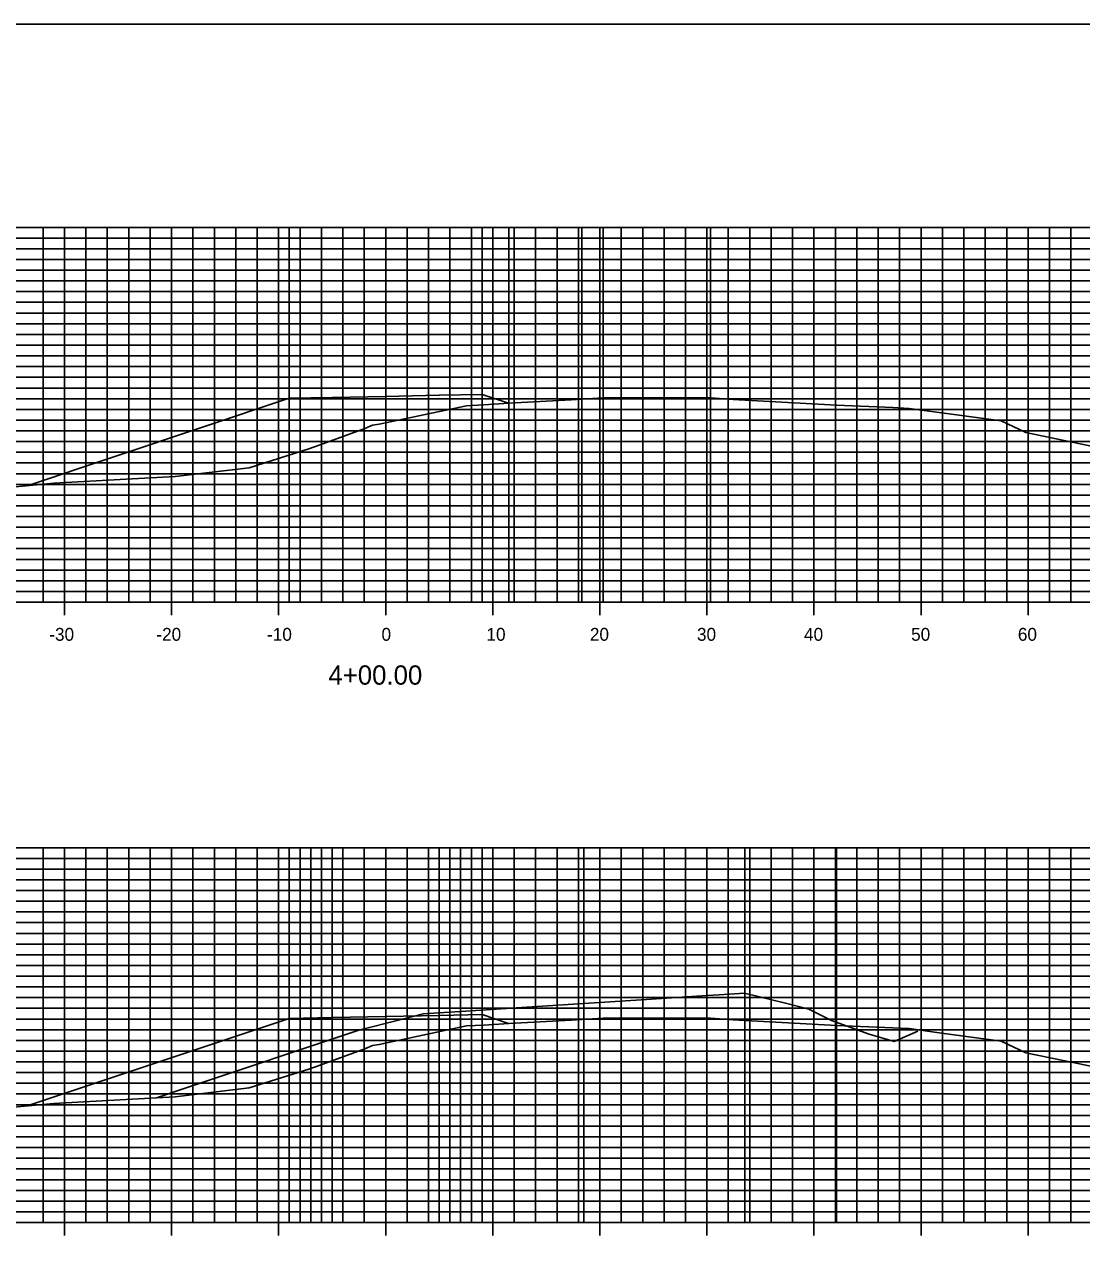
# Model space of a CAD drawing. Extents: x 1405440 to 1409538, y 1842123 to 1843178.
# Drawn here: x 1408848.9 to 1408947.6, y 1842829.8 to 1842943.5 of the extents above; entities that cross this region are included whole.
import ezdxf

# ---------------------------------------------------------------- set-up
doc = ezdxf.new("R2010")
doc.units = 0
for name, color, linetype in [('R_Axis Annot', 7, 'Continuous'), ('R_Exist Surface', 7, 'Continuous'), ('R_Grid_Minor', 7, 'Continuous'), ('R_Grid_Sta', 7, 'Continuous'), ('R_Grid_Tick', 7, 'Continuous'), ('R_Prop Surface', 7, 'Continuous'), ('S_DITCHLINE', 7, 'Continuous'), ('Stage 1_Construction', 7, 'Continuous'), ('Stage 1_Lane', 7, 'Continuous'), ('Stage 1_Removal', 7, 'Continuous'), ('Stage 1_Stripe_4IN_White', 7, 'Continuous'), ('Stage 2_Barrier', 7, 'Continuous'), ('Stage 2_Construction', 7, 'Continuous'), ('Stage 2_Stripe_4IN_White', 7, 'Continuous')]:
    doc.layers.add(name, color=color, linetype=linetype)

msp = doc.modelspace()

# ---------------------------------------------------------------- linework, layer by layer
for p, q in [((1408732.62, 1842924.51), (1409032.62, 1842924.51)), ((1408852.62, 1842889.51), (1408852.62, 1842924.51)), ((1408862.62, 1842889.51), (1408862.62, 1842924.51)), ((1408872.62, 1842889.51), (1408872.62, 1842924.51)), ((1408882.62, 1842889.51), (1408882.62, 1842924.51)), ((1408892.62, 1842889.51), (1408892.62, 1842924.51)), ((1408902.62, 1842889.51), (1408902.62, 1842924.51)), ((1408912.62, 1842889.51), (1408912.62, 1842924.51)), ((1408922.62, 1842889.51), (1408922.62, 1842924.51)), ((1408932.62, 1842889.51), (1408932.62, 1842924.51)), ((1408942.62, 1842889.51), (1408942.62, 1842924.51)), ((1408732.62, 1842919.51), (1409032.62, 1842919.51)), ((1408732.62, 1842914.51), (1409032.62, 1842914.51)), ((1408732.62, 1842909.51), (1409032.62, 1842909.51)), ((1408732.62, 1842904.51), (1409032.62, 1842904.51)), ((1408732.62, 1842899.51), (1409032.62, 1842899.51)), ((1408732.62, 1842894.51), (1409032.62, 1842894.51)), ((1408732.62, 1842889.51), (1409032.62, 1842889.51)), ((1408732.62, 1842889.51), (1409032.62, 1842889.51)), ((1408732.62, 1842866.59), (1409032.62, 1842866.59)), ((1408852.62, 1842831.59), (1408852.62, 1842866.59)), ((1408862.62, 1842831.59), (1408862.62, 1842866.59)), ((1408872.62, 1842831.59), (1408872.62, 1842866.59)), ((1408882.62, 1842831.59), (1408882.62, 1842866.59)), ((1408892.62, 1842831.59), (1408892.62, 1842866.59)), ((1408902.62, 1842831.59), (1408902.62, 1842866.59)), ((1408912.62, 1842831.59), (1408912.62, 1842866.59)), ((1408922.62, 1842831.59), (1408922.62, 1842866.59)), ((1408932.62, 1842831.59), (1408932.62, 1842866.59)), ((1408942.62, 1842831.59), (1408942.62, 1842866.59)), ((1408732.62, 1842861.59), (1409032.62, 1842861.59)), ((1408732.62, 1842856.59), (1409032.62, 1842856.59)), ((1408732.62, 1842851.59), (1409032.62, 1842851.59)), ((1408732.62, 1842846.59), (1409032.62, 1842846.59)), ((1408732.62, 1842841.59), (1409032.62, 1842841.59)), ((1408732.62, 1842836.59), (1409032.62, 1842836.59)), ((1408732.62, 1842831.59), (1409032.62, 1842831.59)), ((1408732.62, 1842831.59), (1409032.62, 1842831.59))]:
    msp.add_line(p, q)
msp.add_lwpolyline([(1408707.62, 1842723.47), (1409047.62, 1842723.47), (1409047.62, 1842943.47), (1408707.62, 1842943.47)], close=True)
at = {"layer": 'R_Exist Surface'}
for points in [[(1408845.09, 1842900.01), (1408851.63, 1842900.62), (1408858.38, 1842901), (1408858.39, 1842901), (1408862.96, 1842901.25), (1408869.87, 1842902.07), (1408875.44, 1842903.83), (1408876.4, 1842904.16), (1408880.67, 1842905.72), (1408881.4, 1842906.03), (1408882, 1842906.14), (1408890.18, 1842907.86), (1408891.78, 1842907.94), (1408894.12, 1842908.09), (1408899.94, 1842908.4), (1408902.94, 1842908.59), (1408908.78, 1842908.6), (1408912.97, 1842908.58), (1408915.06, 1842908.44), (1408924.71, 1842907.9), (1408929.98, 1842907.68), (1408931.51, 1842907.61), (1408934.3, 1842907.22), (1408940.11, 1842906.44), (1408942.42, 1842905.36), (1408951.8, 1842903.41)], [(1408845.09, 1842842.1), (1408851.63, 1842842.71), (1408858.38, 1842843.09), (1408858.39, 1842843.09), (1408862.96, 1842843.33), (1408869.87, 1842844.15), (1408875.44, 1842845.91), (1408876.4, 1842846.24), (1408880.67, 1842847.8), (1408881.4, 1842848.11), (1408882, 1842848.22), (1408890.18, 1842849.94), (1408891.78, 1842850.02), (1408894.12, 1842850.18), (1408899.94, 1842850.48), (1408902.94, 1842850.68), (1408908.78, 1842850.68), (1408912.97, 1842850.66), (1408915.06, 1842850.52), (1408924.71, 1842849.99), (1408929.98, 1842849.76), (1408931.51, 1842849.69), (1408934.3, 1842849.3), (1408940.11, 1842848.53), (1408942.42, 1842847.44), (1408951.8, 1842845.5)]]:
    msp.add_lwpolyline(points, dxfattribs=at)
at = {"layer": 'R_Grid_Minor'}
for p, q in [((1408850.62, 1842889.51), (1408850.62, 1842924.51)), ((1408854.62, 1842889.51), (1408854.62, 1842924.51)), ((1408856.62, 1842889.51), (1408856.62, 1842924.51)), ((1408858.62, 1842889.51), (1408858.62, 1842924.51)), ((1408860.62, 1842889.51), (1408860.62, 1842924.51)), ((1408864.62, 1842889.51), (1408864.62, 1842924.51)), ((1408866.62, 1842889.51), (1408866.62, 1842924.51)), ((1408868.62, 1842889.51), (1408868.62, 1842924.51)), ((1408870.62, 1842889.51), (1408870.62, 1842924.51)), ((1408874.62, 1842889.51), (1408874.62, 1842924.51)), ((1408876.62, 1842889.51), (1408876.62, 1842924.51)), ((1408878.62, 1842889.51), (1408878.62, 1842924.51)), ((1408880.62, 1842889.51), (1408880.62, 1842924.51)), ((1408884.62, 1842889.51), (1408884.62, 1842924.51)), ((1408886.62, 1842889.51), (1408886.62, 1842924.51)), ((1408888.62, 1842889.51), (1408888.62, 1842924.51)), ((1408890.62, 1842889.51), (1408890.62, 1842924.51)), ((1408894.62, 1842889.51), (1408894.62, 1842924.51)), ((1408896.62, 1842889.51), (1408896.62, 1842924.51)), ((1408898.62, 1842889.51), (1408898.62, 1842924.51)), ((1408900.62, 1842889.51), (1408900.62, 1842924.51)), ((1408904.62, 1842889.51), (1408904.62, 1842924.51)), ((1408906.62, 1842889.51), (1408906.62, 1842924.51)), ((1408908.62, 1842889.51), (1408908.62, 1842924.51)), ((1408910.62, 1842889.51), (1408910.62, 1842924.51)), ((1408914.62, 1842889.51), (1408914.62, 1842924.51)), ((1408916.62, 1842889.51), (1408916.62, 1842924.51)), ((1408918.62, 1842889.51), (1408918.62, 1842924.51)), ((1408920.62, 1842889.51), (1408920.62, 1842924.51)), ((1408924.62, 1842889.51), (1408924.62, 1842924.51)), ((1408926.62, 1842889.51), (1408926.62, 1842924.51)), ((1408928.62, 1842889.51), (1408928.62, 1842924.51)), ((1408930.62, 1842889.51), (1408930.62, 1842924.51)), ((1408934.62, 1842889.51), (1408934.62, 1842924.51)), ((1408936.62, 1842889.51), (1408936.62, 1842924.51)), ((1408938.62, 1842889.51), (1408938.62, 1842924.51)), ((1408940.62, 1842889.51), (1408940.62, 1842924.51)), ((1408944.62, 1842889.51), (1408944.62, 1842924.51)), ((1408946.62, 1842889.51), (1408946.62, 1842924.51)), ((1408732.62, 1842923.51), (1409032.62, 1842923.51)), ((1408732.62, 1842922.51), (1409032.62, 1842922.51)), ((1408732.62, 1842921.51), (1409032.62, 1842921.51)), ((1408732.62, 1842920.51), (1409032.62, 1842920.51)), ((1408732.62, 1842918.51), (1409032.62, 1842918.51)), ((1408732.62, 1842917.51), (1409032.62, 1842917.51)), ((1408732.62, 1842916.51), (1409032.62, 1842916.51)), ((1408732.62, 1842915.51), (1409032.62, 1842915.51)), ((1408732.62, 1842913.51), (1409032.62, 1842913.51)), ((1408732.62, 1842912.51), (1409032.62, 1842912.51)), ((1408732.62, 1842911.51), (1409032.62, 1842911.51)), ((1408732.62, 1842910.51), (1409032.62, 1842910.51)), ((1408732.62, 1842908.51), (1409032.62, 1842908.51)), ((1408732.62, 1842907.51), (1409032.62, 1842907.51)), ((1408732.62, 1842906.51), (1409032.62, 1842906.51)), ((1408732.62, 1842905.51), (1409032.62, 1842905.51)), ((1408732.62, 1842903.51), (1409032.62, 1842903.51)), ((1408732.62, 1842902.51), (1409032.62, 1842902.51)), ((1408732.62, 1842901.51), (1409032.62, 1842901.51)), ((1408732.62, 1842900.51), (1409032.62, 1842900.51)), ((1408732.62, 1842898.51), (1409032.62, 1842898.51)), ((1408732.62, 1842897.51), (1409032.62, 1842897.51)), ((1408732.62, 1842896.51), (1409032.62, 1842896.51)), ((1408732.62, 1842895.51), (1409032.62, 1842895.51)), ((1408732.62, 1842893.51), (1409032.62, 1842893.51)), ((1408732.62, 1842892.51), (1409032.62, 1842892.51)), ((1408732.62, 1842891.51), (1409032.62, 1842891.51)), ((1408732.62, 1842890.51), (1409032.62, 1842890.51)), ((1408850.62, 1842831.59), (1408850.62, 1842866.59)), ((1408854.62, 1842831.59), (1408854.62, 1842866.59)), ((1408856.62, 1842831.59), (1408856.62, 1842866.59)), ((1408858.62, 1842831.59), (1408858.62, 1842866.59)), ((1408860.62, 1842831.59), (1408860.62, 1842866.59)), ((1408864.62, 1842831.59), (1408864.62, 1842866.59)), ((1408866.62, 1842831.59), (1408866.62, 1842866.59)), ((1408868.62, 1842831.59), (1408868.62, 1842866.59)), ((1408870.62, 1842831.59), (1408870.62, 1842866.59)), ((1408874.62, 1842831.59), (1408874.62, 1842866.59)), ((1408876.62, 1842831.59), (1408876.62, 1842866.59)), ((1408878.62, 1842831.59), (1408878.62, 1842866.59)), ((1408880.62, 1842831.59), (1408880.62, 1842866.59)), ((1408884.62, 1842831.59), (1408884.62, 1842866.59)), ((1408886.62, 1842831.59), (1408886.62, 1842866.59)), ((1408888.62, 1842831.59), (1408888.62, 1842866.59)), ((1408890.62, 1842831.59), (1408890.62, 1842866.59)), ((1408894.62, 1842831.59), (1408894.62, 1842866.59)), ((1408896.62, 1842831.59), (1408896.62, 1842866.59)), ((1408898.62, 1842831.59), (1408898.62, 1842866.59)), ((1408900.62, 1842831.59), (1408900.62, 1842866.59)), ((1408904.62, 1842831.59), (1408904.62, 1842866.59)), ((1408906.62, 1842831.59), (1408906.62, 1842866.59)), ((1408908.62, 1842831.59), (1408908.62, 1842866.59)), ((1408910.62, 1842831.59), (1408910.62, 1842866.59)), ((1408914.62, 1842831.59), (1408914.62, 1842866.59)), ((1408916.62, 1842831.59), (1408916.62, 1842866.59)), ((1408918.62, 1842831.59), (1408918.62, 1842866.59)), ((1408920.62, 1842831.59), (1408920.62, 1842866.59)), ((1408924.62, 1842831.59), (1408924.62, 1842866.59)), ((1408926.62, 1842831.59), (1408926.62, 1842866.59)), ((1408928.62, 1842831.59), (1408928.62, 1842866.59)), ((1408930.62, 1842831.59), (1408930.62, 1842866.59)), ((1408934.62, 1842831.59), (1408934.62, 1842866.59)), ((1408936.62, 1842831.59), (1408936.62, 1842866.59)), ((1408938.62, 1842831.59), (1408938.62, 1842866.59)), ((1408940.62, 1842831.59), (1408940.62, 1842866.59)), ((1408944.62, 1842831.59), (1408944.62, 1842866.59)), ((1408946.62, 1842831.59), (1408946.62, 1842866.59)), ((1408732.62, 1842865.59), (1409032.62, 1842865.59)), ((1408732.62, 1842864.59), (1409032.62, 1842864.59)), ((1408732.62, 1842863.59), (1409032.62, 1842863.59)), ((1408732.62, 1842862.59), (1409032.62, 1842862.59)), ((1408732.62, 1842860.59), (1409032.62, 1842860.59)), ((1408732.62, 1842859.59), (1409032.62, 1842859.59)), ((1408732.62, 1842858.59), (1409032.62, 1842858.59)), ((1408732.62, 1842857.59), (1409032.62, 1842857.59)), ((1408732.62, 1842855.59), (1409032.62, 1842855.59)), ((1408732.62, 1842854.59), (1409032.62, 1842854.59)), ((1408732.62, 1842853.59), (1409032.62, 1842853.59)), ((1408732.62, 1842852.59), (1409032.62, 1842852.59)), ((1408732.62, 1842850.59), (1409032.62, 1842850.59)), ((1408732.62, 1842849.59), (1409032.62, 1842849.59)), ((1408732.62, 1842848.59), (1409032.62, 1842848.59)), ((1408732.62, 1842847.59), (1409032.62, 1842847.59)), ((1408732.62, 1842845.59), (1409032.62, 1842845.59)), ((1408732.62, 1842844.59), (1409032.62, 1842844.59)), ((1408732.62, 1842843.59), (1409032.62, 1842843.59)), ((1408732.62, 1842842.59), (1409032.62, 1842842.59)), ((1408732.62, 1842840.59), (1409032.62, 1842840.59)), ((1408732.62, 1842839.59), (1409032.62, 1842839.59)), ((1408732.62, 1842838.59), (1409032.62, 1842838.59)), ((1408732.62, 1842837.59), (1409032.62, 1842837.59)), ((1408732.62, 1842835.59), (1409032.62, 1842835.59)), ((1408732.62, 1842834.59), (1409032.62, 1842834.59)), ((1408732.62, 1842833.59), (1409032.62, 1842833.59)), ((1408732.62, 1842832.59), (1409032.62, 1842832.59))]:
    msp.add_line(p, q, dxfattribs=at)
at = {"layer": 'R_Grid_Tick'}
for p, q in [((1408850.62, 1842889.51), (1408850.62, 1842890.11)), ((1408852.62, 1842888.31), (1408852.62, 1842890.71)), ((1408854.62, 1842889.51), (1408854.62, 1842890.11)), ((1408856.62, 1842889.51), (1408856.62, 1842890.11)), ((1408858.62, 1842889.51), (1408858.62, 1842890.11)), ((1408860.62, 1842889.51), (1408860.62, 1842890.11)), ((1408862.62, 1842888.31), (1408862.62, 1842890.71)), ((1408864.62, 1842889.51), (1408864.62, 1842890.11)), ((1408866.62, 1842889.51), (1408866.62, 1842890.11)), ((1408868.62, 1842889.51), (1408868.62, 1842890.11)), ((1408870.62, 1842889.51), (1408870.62, 1842890.11)), ((1408872.62, 1842888.31), (1408872.62, 1842890.71)), ((1408874.62, 1842889.51), (1408874.62, 1842890.11)), ((1408876.62, 1842889.51), (1408876.62, 1842890.11)), ((1408878.62, 1842889.51), (1408878.62, 1842890.11)), ((1408880.62, 1842889.51), (1408880.62, 1842890.11)), ((1408882.62, 1842888.31), (1408882.62, 1842890.71)), ((1408884.62, 1842889.51), (1408884.62, 1842890.11)), ((1408886.62, 1842889.51), (1408886.62, 1842890.11)), ((1408888.62, 1842889.51), (1408888.62, 1842890.11)), ((1408890.62, 1842889.51), (1408890.62, 1842890.11)), ((1408892.62, 1842888.31), (1408892.62, 1842890.71)), ((1408894.62, 1842889.51), (1408894.62, 1842890.11)), ((1408896.62, 1842889.51), (1408896.62, 1842890.11)), ((1408898.62, 1842889.51), (1408898.62, 1842890.11)), ((1408900.62, 1842889.51), (1408900.62, 1842890.11)), ((1408902.62, 1842888.31), (1408902.62, 1842890.71)), ((1408904.62, 1842889.51), (1408904.62, 1842890.11)), ((1408906.62, 1842889.51), (1408906.62, 1842890.11)), ((1408908.62, 1842889.51), (1408908.62, 1842890.11)), ((1408910.62, 1842889.51), (1408910.62, 1842890.11)), ((1408912.62, 1842888.31), (1408912.62, 1842890.71)), ((1408914.62, 1842889.51), (1408914.62, 1842890.11)), ((1408916.62, 1842889.51), (1408916.62, 1842890.11)), ((1408918.62, 1842889.51), (1408918.62, 1842890.11)), ((1408920.62, 1842889.51), (1408920.62, 1842890.11)), ((1408922.62, 1842888.31), (1408922.62, 1842890.71)), ((1408924.62, 1842889.51), (1408924.62, 1842890.11)), ((1408926.62, 1842889.51), (1408926.62, 1842890.11)), ((1408928.62, 1842889.51), (1408928.62, 1842890.11)), ((1408930.62, 1842889.51), (1408930.62, 1842890.11)), ((1408932.62, 1842888.31), (1408932.62, 1842890.71)), ((1408934.62, 1842889.51), (1408934.62, 1842890.11)), ((1408936.62, 1842889.51), (1408936.62, 1842890.11)), ((1408938.62, 1842889.51), (1408938.62, 1842890.11)), ((1408940.62, 1842889.51), (1408940.62, 1842890.11)), ((1408942.62, 1842888.31), (1408942.62, 1842890.71)), ((1408944.62, 1842889.51), (1408944.62, 1842890.11)), ((1408946.62, 1842889.51), (1408946.62, 1842890.11)), ((1408850.62, 1842831.59), (1408850.62, 1842832.19)), ((1408852.62, 1842830.39), (1408852.62, 1842832.79)), ((1408854.62, 1842831.59), (1408854.62, 1842832.19)), ((1408856.62, 1842831.59), (1408856.62, 1842832.19)), ((1408858.62, 1842831.59), (1408858.62, 1842832.19)), ((1408860.62, 1842831.59), (1408860.62, 1842832.19)), ((1408862.62, 1842830.39), (1408862.62, 1842832.79)), ((1408864.62, 1842831.59), (1408864.62, 1842832.19)), ((1408866.62, 1842831.59), (1408866.62, 1842832.19)), ((1408868.62, 1842831.59), (1408868.62, 1842832.19)), ((1408870.62, 1842831.59), (1408870.62, 1842832.19)), ((1408872.62, 1842830.39), (1408872.62, 1842832.79)), ((1408874.62, 1842831.59), (1408874.62, 1842832.19)), ((1408876.62, 1842831.59), (1408876.62, 1842832.19)), ((1408878.62, 1842831.59), (1408878.62, 1842832.19)), ((1408880.62, 1842831.59), (1408880.62, 1842832.19)), ((1408882.62, 1842830.39), (1408882.62, 1842832.79)), ((1408884.62, 1842831.59), (1408884.62, 1842832.19)), ((1408886.62, 1842831.59), (1408886.62, 1842832.19)), ((1408888.62, 1842831.59), (1408888.62, 1842832.19)), ((1408890.62, 1842831.59), (1408890.62, 1842832.19)), ((1408892.62, 1842830.39), (1408892.62, 1842832.79)), ((1408894.62, 1842831.59), (1408894.62, 1842832.19)), ((1408896.62, 1842831.59), (1408896.62, 1842832.19)), ((1408898.62, 1842831.59), (1408898.62, 1842832.19)), ((1408900.62, 1842831.59), (1408900.62, 1842832.19)), ((1408902.62, 1842830.39), (1408902.62, 1842832.79)), ((1408904.62, 1842831.59), (1408904.62, 1842832.19)), ((1408906.62, 1842831.59), (1408906.62, 1842832.19)), ((1408908.62, 1842831.59), (1408908.62, 1842832.19)), ((1408910.62, 1842831.59), (1408910.62, 1842832.19)), ((1408912.62, 1842830.39), (1408912.62, 1842832.79)), ((1408914.62, 1842831.59), (1408914.62, 1842832.19)), ((1408916.62, 1842831.59), (1408916.62, 1842832.19)), ((1408918.62, 1842831.59), (1408918.62, 1842832.19)), ((1408920.62, 1842831.59), (1408920.62, 1842832.19)), ((1408922.62, 1842830.39), (1408922.62, 1842832.79)), ((1408924.62, 1842831.59), (1408924.62, 1842832.19)), ((1408926.62, 1842831.59), (1408926.62, 1842832.19)), ((1408928.62, 1842831.59), (1408928.62, 1842832.19)), ((1408930.62, 1842831.59), (1408930.62, 1842832.19)), ((1408932.62, 1842830.39), (1408932.62, 1842832.79)), ((1408934.62, 1842831.59), (1408934.62, 1842832.19)), ((1408936.62, 1842831.59), (1408936.62, 1842832.19)), ((1408938.62, 1842831.59), (1408938.62, 1842832.19)), ((1408940.62, 1842831.59), (1408940.62, 1842832.19)), ((1408942.62, 1842830.39), (1408942.62, 1842832.79)), ((1408944.62, 1842831.59), (1408944.62, 1842832.19)), ((1408946.62, 1842831.59), (1408946.62, 1842832.19))]:
    msp.add_line(p, q, dxfattribs=at)
at = {"layer": 'R_Prop Surface'}
for points in [[(1408849.13, 1842900.39), (1408873.62, 1842908.55), (1408877.62, 1842908.63), (1408882.62, 1842908.73), (1408887.62, 1842908.83), (1408891.62, 1842908.91), (1408894.09, 1842908.09)], [(1408861.2, 1842843.24), (1408863.72, 1842844.08), (1408880.11, 1842849.55), (1408884.06, 1842850.54), (1408886.12, 1842851.06), (1408888.58, 1842851.22), (1408890.12, 1842851.32), (1408894.83, 1842851.62), (1408901.13, 1842852.04), (1408906.97, 1842852.41), (1408912.14, 1842852.75), (1408913.76, 1842852.86), (1408916.14, 1842853.01), (1408919.96, 1842852.06), (1408922.15, 1842851.51), (1408924.25, 1842850.46), (1408927.77, 1842849.19), (1408930.11, 1842848.48), (1408932.33, 1842849.45)], [(1408849.13, 1842842.47), (1408873.62, 1842850.64), (1408877.62, 1842850.72), (1408882.62, 1842850.82), (1408887.62, 1842850.92), (1408891.62, 1842851), (1408894.09, 1842850.17)]]:
    msp.add_lwpolyline(points, dxfattribs=at)
at = {"layer": 'S_DITCHLINE'}
msp.add_line((1408924.71, 1842831.59), (1408924.71, 1842866.59), dxfattribs=at)
at = {"layer": 'Stage 1_Construction'}
for p, q in [((1408873.62, 1842889.51), (1408873.62, 1842924.51)), ((1408891.62, 1842889.51), (1408891.62, 1842924.51))]:
    msp.add_line(p, q, dxfattribs=at)
at = {"layer": 'Stage 1_Lane'}
msp.add_line((1408912.97, 1842889.51), (1408912.97, 1842924.51), dxfattribs=at)
at = {"layer": 'Stage 1_Removal'}
for p, q in [((1408894.12, 1842889.51), (1408894.12, 1842924.51)), ((1408900.94, 1842889.51), (1408900.94, 1842924.51))]:
    msp.add_line(p, q, dxfattribs=at)
at = {"layer": 'Stage 1_Stripe_4IN_White'}
msp.add_line((1408902.94, 1842889.51), (1408902.94, 1842924.51), dxfattribs=at)
at = {"layer": 'Stage 2_Barrier'}
for p, q in [((1408873.62, 1842831.59), (1408873.62, 1842866.59)), ((1408875.62, 1842831.59), (1408875.62, 1842866.59)), ((1408889.62, 1842831.59), (1408889.62, 1842866.59)), ((1408891.62, 1842831.59), (1408891.62, 1842866.59))]:
    msp.add_line(p, q, dxfattribs=at)
at = {"layer": 'Stage 2_Construction'}
for p, q in [((1408901.14, 1842831.59), (1408901.14, 1842866.59)), ((1408916.15, 1842831.59), (1408916.15, 1842866.59))]:
    msp.add_line(p, q, dxfattribs=at)
at = {"layer": 'Stage 2_Stripe_4IN_White'}
for p, q in [((1408877.62, 1842831.59), (1408877.62, 1842866.59)), ((1408887.62, 1842831.59), (1408887.62, 1842866.59))]:
    msp.add_line(p, q, dxfattribs=at)

# ---------------------------------------------------------------- texts
at = {"layer": 'R_Axis Annot'}
for s, p in [('-30', (1408851.2, 1842885.91)), ('-20', (1408861.2, 1842885.91)), ('-10', (1408871.54, 1842885.91)), ('0', (1408882.23, 1842885.91)), ('10', (1408892.03, 1842885.91)), ('20', (1408901.69, 1842885.91)), ('30', (1408911.69, 1842885.91)), ('40', (1408921.69, 1842885.91)), ('50', (1408931.69, 1842885.91)), ('60', (1408941.66, 1842885.91))]:
    msp.add_text(s, height=1.2, dxfattribs=at).set_placement(p)
at = {"layer": 'R_Grid_Sta'}
msp.add_text('4+00.00', height=1.8, dxfattribs=at).set_placement((1408877.27, 1842881.81))

doc.saveas('drawing.dxf')
